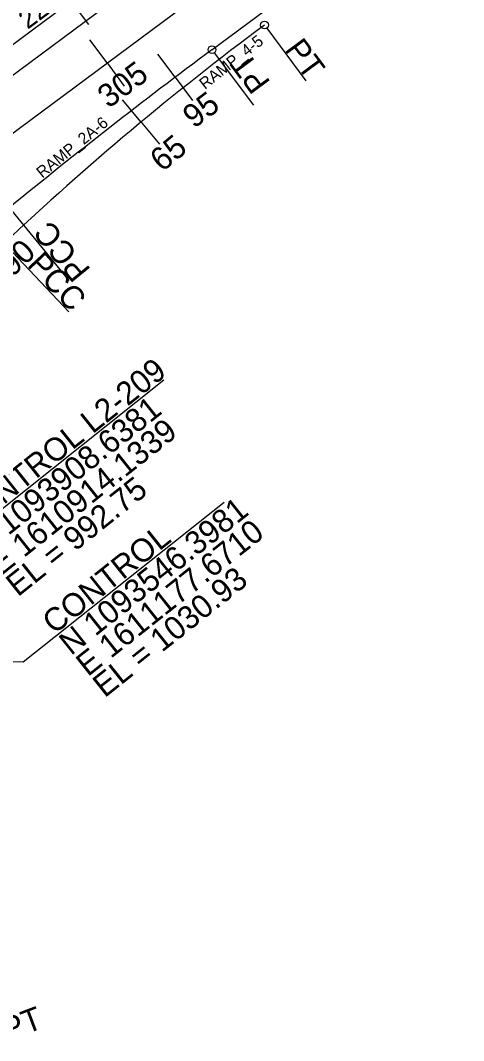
# Model space of a CAD drawing. Extents: x 1603447 to 1622636, y 1083818 to 1103958.
# Drawn here: x 1611793 to 1612712, y 1092753 to 1094869 of the extents above; entities that cross this region are included whole.
import ezdxf

# ---------------------------------------------------------------- set-up
doc = ezdxf.new("R2010")
doc.units = 0
for name, color, linetype in [('Level 1', 7, 'Continuous'), ('RD_HC_Points', 7, 'Continuous'), ('RD_HC_SUR_Bearing_TX400', 7, 'Continuous'), ('RD_HC_SUR_CL400', 7, 'Continuous'), ('RD_HC_SUR_PC_PT_400', 7, 'Continuous'), ('RD_HC_SUR_Tic400', 7, 'Continuous'), ('RD_HC_SUR_TX_Sta400', 7, 'Continuous'), ('RD_TX_Misc1', 7, 'Continuous')]:
    doc.layers.add(name, color=color, linetype=linetype)

msp = doc.modelspace()

# ---------------------------------------------------------------- linework, layer by layer
at = {"layer": 'RD_HC_Points'}
for p, q in [((1612090.7, 1094122.5), (1611685.6, 1093800.2)), ((1612215.2, 1093868.9), (1611865.6, 1093590.8))]:
    msp.add_line(p, q, dxfattribs=at)
msp.add_lwpolyline([(1611865.6, 1093590.8), (1611798.8, 1093537.7), (1611177.7, 1093546.4)], dxfattribs=at)
at = {"layer": 'RD_HC_SUR_CL400'}
for p, q in [((1614436.6, 1096731.7), (1611265.2, 1094374.2)), ((1609261, 1092765), (1614429, 1096606.7)), ((1612190.2, 1094808.2), (1612928.5, 1095357.1)), ((1612058.8, 1095027.6), (1611687.1, 1094751.4))]:
    msp.add_line(p, q, dxfattribs=at)
for centre, radius, end in [((1615878.6, 1090044), 6000, 133.35895), ((1619021.1, 1085619), 11450, 129.29258)]:
    msp.add_arc(centre, radius, 126.62559, end, dxfattribs=at)
at = {"layer": 'RD_HC_SUR_PC_PT_400'}
for p, q in [((1612303.9, 1094852.8), (1612384.9, 1094743.8)), ((1612195, 1094801.8), (1612276, 1094692.8)), ((1611775.1, 1094474.2), (1611893.8, 1094329.2)), ((1611764.7, 1094400.5), (1611893.4, 1094264.2))]:
    msp.add_line(p, q, dxfattribs=at)
for centre in [(1612299.1, 1094859.3), (1612190.2, 1094808.2)]:
    msp.add_circle(centre, 8, dxfattribs=at)
at = {"layer": 'RD_HC_SUR_Tic400'}
for p, q in [((1611898.3, 1094908.3), (1611934.1, 1094860.2)), ((1611928.3, 1094867.1), (1611928.3, 1094867.1)), ((1611818, 1094848.7), (1611818, 1094848.7)), ((1611972.6, 1094780.7), (1611936.8, 1094828.8)), ((1612052.8, 1094840.3), (1612052.8, 1094840.3)), ((1612278.7, 1094844), (1612278.7, 1094844)), ((1612278.7, 1094844), (1612278.7, 1094844)), ((1611848.1, 1094807.5), (1611848.1, 1094807.5)), ((1612193.9, 1094811), (1612193.9, 1094811)), ((1612113.9, 1094751), (1612077.7, 1094798.8)), ((1611972.6, 1094780.7), (1612008.4, 1094732.5)), ((1612199.2, 1094783.4), (1612199.2, 1094783.4)), ((1612199.2, 1094783.4), (1612199.2, 1094783.4)), ((1612113.9, 1094751), (1612150.1, 1094703.1)), ((1611892.3, 1094721), (1611892.3, 1094721)), ((1612043.3, 1094658.1), (1612004.9, 1094704.3)), ((1612120.7, 1094721.4), (1612120.7, 1094721.4)), ((1612120.7, 1094721.4), (1612120.7, 1094721.4)), ((1612034.4, 1094690.3), (1612034.4, 1094690.3)), ((1611812, 1094661.4), (1611812, 1094661.4)), ((1612043.3, 1094658.1), (1612081.7, 1094612)), ((1611955.4, 1094629), (1611955.4, 1094629)), ((1611966.9, 1094593.6), (1611966.9, 1094593.6)), ((1611966.9, 1094593.6), (1611966.9, 1094593.6)), ((1611877, 1094566.9), (1611877, 1094566.9)), ((1611891.7, 1094527.7), (1611891.7, 1094527.7)), ((1611891.7, 1094527.7), (1611891.7, 1094527.7)), ((1611799.2, 1094504.2), (1611799.2, 1094504.2)), ((1611817.5, 1094460.7), (1611817.5, 1094460.7))]:
    msp.add_line(p, q, dxfattribs=at)

# ---------------------------------------------------------------- texts
at = {"layer": 'Level 1'}
for s, rotation, p in [('305', 36.6256, (1611976, 1094685.1)), ('95', 37.1031, (1612153, 1094643.3)), ('65', 39.7335, (1612087.1, 1094553.1))]:
    msp.add_text(s, height=48, rotation=rotation, dxfattribs=at).set_placement(p)
at = {"layer": 'RD_HC_Points'}
for s, p in [('CONTROL L2-209', (1611683.1, 1093803.4)), ('N 1093908.6381', (1611717.9, 1093759.5)), ('E 1610914.1339', (1611752.8, 1093715.7)), ('EL = 992.75', (1611787.7, 1093671.9)), ('N 1093546.3981', (1611898, 1093550.1)), ('E 1611177.6710', (1611932.9, 1093506.3)), ('CONTROL ', (1611863.1, 1093593.9)), ('EL = 1030.93', (1611967.7, 1093462.5))]:
    msp.add_text(s, height=48, rotation=38.4995, dxfattribs=at).set_placement(p)
at = {"layer": 'RD_HC_SUR_Bearing_TX400'}
msp.add_text('S 53%%d 22\' 28" W', height=40, rotation=36.6256, dxfattribs=at).set_placement((1611690.7, 1094762.1))
at = {"layer": 'RD_HC_SUR_PC_PT_400'}
for s, rotation, p in [('PT', 306.6256, (1612339.5, 1094808.3)), ('PT', 126.6256, (1612313, 1094740.6)), ('PCC', 129.2926, (1611940.5, 1094351.9)), ('PCC', 313.359, (1611805.3, 1094360.5)), ('PT', 20.7167, (1611766.1, 1092750.7))]:
    msp.add_text(s, height=48, rotation=rotation, dxfattribs=at).set_placement(p)
at = {"layer": 'RD_HC_SUR_TX_Sta400'}
msp.add_text('90', height=48, rotation=43.6117, dxfattribs=at).set_placement((1611776.2, 1094334.9))
at = {"layer": 'RD_TX_Misc1'}
for s, rotation, p in [('RAMP_4-5', 38.2125, (1612175.6, 1094724.6)), ('RAMP_2A-6', 38.8639, (1611838.3, 1094540.5))]:
    msp.add_text(s, height=24, rotation=rotation, dxfattribs=at).set_placement(p)

doc.saveas('drawing.dxf')
